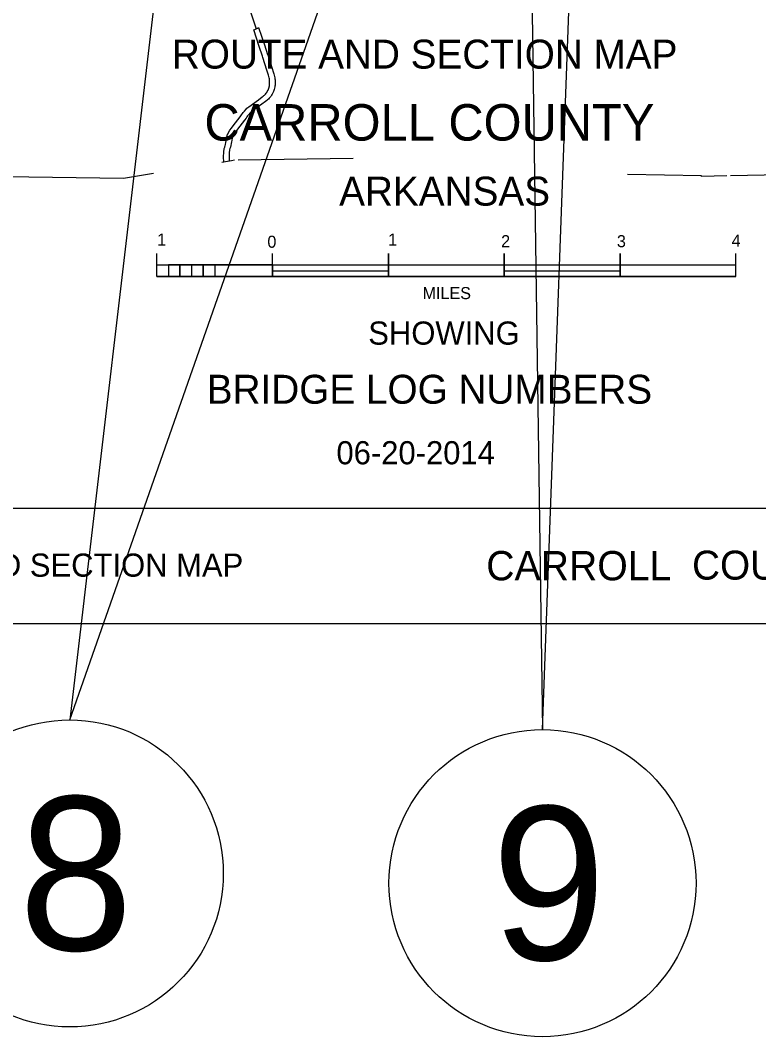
# Model space of a CAD drawing. Extents: x 77230 to 630905, y 790554 to 1662844.
# Drawn here: x 544436 to 578093, y 1464500 to 1510846 of the extents above; entities that cross this region are included whole.
import ezdxf

# ---------------------------------------------------------------- set-up
doc = ezdxf.new("R2010")
doc.units = 0
for name, color, linetype in [('Level 10', 7, 'Continuous'), ('Level 28', 7, 'Continuous'), ('Level 41', 7, 'Continuous'), ('Level 43', 7, 'Continuous')]:
    doc.layers.add(name, color=color, linetype=linetype)

msp = doc.modelspace()

# ---------------------------------------------------------------- linework, layer by layer
at = {"layer": 'Level 10'}
for points in [[(554148, 1513919), (554167, 1513776), (554228, 1513500), (554320, 1513168), (554737, 1511840), (555112, 1510683)], [(553709, 1504836), (553714, 1504879), (553719, 1504915), (553724, 1504948), (553735, 1504998), (553752, 1505059), (553761, 1505094), (553769, 1505124), (553781, 1505182), (553798, 1505274), (553816, 1505353), (553827, 1505409), (553850, 1505541), (553858, 1505578), (553872, 1505620), (553891, 1505662), (553932, 1505731), (553992, 1505830), (554056, 1505924), (554144, 1506035), (554457, 1506448), (554523, 1506537), (554567, 1506596), (554599, 1506638), (554654, 1506708), (554725, 1506793), (554768, 1506837), (554810, 1506874), (554853, 1506908), (555292, 1507223), (555466, 1507352), (555512, 1507387), (555543, 1507412), (555572, 1507437), (555598, 1507463), (555614, 1507480), (555644, 1507520), (555671, 1507562), (555694, 1507602), (555728, 1507660), (555740, 1507681), (555748, 1507697), (555753, 1507714), (555762, 1507748), (555790, 1507866), (555796, 1507890), (555799, 1507916), (555801, 1507958), (555800, 1508043), (555797, 1508122), (555793, 1508153), (555789, 1508185), (555781, 1508222), (555749, 1508341), (555721, 1508430), (555678, 1508569), (555494, 1509146), (555473, 1509207), (555322, 1509655), (555073, 1510405)], [(555299, 1510518), (555559, 1509734), (555710, 1509287), (555731, 1509224), (555916, 1508644), (555960, 1508504), (555989, 1508411), (556023, 1508282), (556035, 1508231), (556041, 1508184), (556046, 1508140), (556050, 1508049), (556051, 1507954), (556048, 1507894), (556042, 1507845), (556033, 1507809), (556005, 1507688), (555993, 1507644), (555980, 1507604), (555961, 1507564), (555944, 1507535), (555911, 1507477), (555884, 1507431), (555849, 1507377), (555808, 1507322), (555779, 1507290), (555742, 1507253), (555703, 1507220), (555666, 1507190), (555616, 1507152), (555440, 1507021), (555003, 1506708), (554971, 1506683), (554940, 1506655), (554910, 1506624), (554848, 1506551), (554796, 1506484), (554766, 1506445), (554723, 1506388), (554657, 1506298), (554341, 1505882), (554257, 1505776), (554202, 1505696), (554147, 1505603), (554113, 1505546), (554105, 1505530), (554100, 1505513), (554096, 1505494), (554073, 1505362), (554060, 1505300), (554043, 1505223), (554026, 1505135), (554013, 1505067), (554003, 1505029), (553993, 1504994), (553978, 1504939), (553970, 1504901), (553966, 1504876), (553962, 1504847), (553959, 1504820)], [(555112, 1510683), (555187, 1510458)], [(553959, 1504424), (553710, 1504383), (553704, 1504617), (553709, 1504836)], [(553959, 1504820), (553954, 1504617), (553959, 1504424)]]:
    msp.add_lwpolyline(points, dxfattribs=at)
msp.add_arc((554369, 1512098), 1833, 292.5727, 300.4716, dxfattribs=at)
at = {"layer": 'Level 28'}
for p, q in [((550656, 1499692), (550656, 1500220)), ((555936, 1499692), (555936, 1500220)), ((561216, 1499692), (561216, 1500220)), ((561216, 1500220), (561216, 1499692)), ((566496, 1499692), (566496, 1500220)), ((566496, 1500220), (566496, 1499692)), ((571776, 1499692), (571776, 1500220)), ((571776, 1500220), (571776, 1499692)), ((577056, 1499164), (577056, 1500220)), ((550656, 1499164), (550656, 1499692)), ((550656, 1499692), (550656, 1499692)), ((550656, 1499692), (555936, 1499692)), ((550656, 1499692), (551184, 1499692)), ((551184, 1499692), (551184, 1499692)), ((551712, 1499692), (551184, 1499692)), ((551184, 1499692), (551184, 1499692)), ((551184, 1499692), (551184, 1499164)), ((552240, 1499692), (551712, 1499692)), ((551712, 1499692), (551712, 1499692)), ((551712, 1499692), (551712, 1499692)), ((551712, 1499692), (551712, 1499164)), ((551712, 1499164), (551712, 1499692)), ((552768, 1499692), (552240, 1499692)), ((552240, 1499692), (552240, 1499692)), ((552240, 1499692), (552240, 1499692)), ((552240, 1499692), (552240, 1499164)), ((553296, 1499692), (552768, 1499692)), ((552768, 1499692), (552768, 1499692)), ((552768, 1499692), (552768, 1499164)), ((552768, 1499164), (552768, 1499692)), ((553296, 1499692), (553373, 1499697)), ((555936, 1499692), (553296, 1499692)), ((553296, 1499692), (553296, 1499164)), ((555936, 1499692), (555936, 1499692)), ((555936, 1499692), (555936, 1499164)), ((555936, 1499164), (555936, 1499692)), ((555936, 1499692), (561216, 1499692)), ((555936, 1499164), (555936, 1499428)), ((555936, 1499428), (555936, 1499428)), ((555936, 1499428), (561216, 1499428)), ((561216, 1499692), (561216, 1499164)), ((561216, 1499164), (561216, 1499692)), ((561216, 1499692), (566496, 1499692)), ((566496, 1499692), (566496, 1499692)), ((566496, 1499692), (566496, 1499164)), ((566496, 1499164), (566496, 1499692)), ((566496, 1499692), (571776, 1499692)), ((566496, 1499164), (566496, 1499420)), ((566496, 1499420), (566496, 1499420)), ((566496, 1499420), (571776, 1499420)), ((571776, 1499692), (571776, 1499164)), ((571776, 1499164), (571776, 1499692)), ((571776, 1499692), (577056, 1499692)), ((550656, 1499164), (577056, 1499164)), ((577056, 1499164), (550656, 1499164)), ((311736, 1488604), (586296, 1488604)), ((591576, 1483324), (295896, 1483324))]:
    msp.add_line(p, q, dxfattribs=at)
at = {"layer": 'Level 41'}
for points in [[(567679, 1517517), (568239, 1478500), (569738, 1519525)], [(550532, 1511658), (546688, 1478945), (558497, 1512665)]]:
    msp.add_lwpolyline(points, dxfattribs=at)
for centre in [(546688, 1471945), (568239, 1471500)]:
    msp.add_circle(centre, 7000, dxfattribs=at)
at = {"layer": 'Level 43'}
for points in [[(553709, 1504383), (553614, 1504367)], [(554055, 1504440), (553973, 1504426)], [(554204, 1504465), (554055, 1504440)], [(559611, 1504543), (554360, 1504475)], [(550513, 1503855), (549139, 1503629), (543739, 1503707), (543107, 1503717)], [(576641, 1503750), (575485, 1503727), (575485, 1503753), (572118, 1503814)], [(584379, 1503890), (580655, 1503830), (580648, 1503830), (576808, 1503754)]]:
    msp.add_lwpolyline(points, dxfattribs=at)

# ---------------------------------------------------------------- texts
at = {"layer": 'Level 28'}
for s, height, p in [('ROUTE AND SECTION MAP', 1320, (551344, 1508645)), ('CARROLL COUNTY', 1663, (552826, 1505361)), ('ARKANSAS', 1320, (558969, 1502397)), ('1', 550, (550672, 1500575)), ('0', 550, (555698, 1500476)), ('1', 550, (561204, 1500575)), ('2', 550, (566352, 1500500)), ('3', 550, (571631, 1500500)), ('4', 550, (576860, 1500525)), ('MILES', 550, (562771, 1498133)), ('SHOWING', 1056, (560297, 1496057)), ('BRIDGE LOG NUMBERS', 1320, (552933, 1493363)), ('06-20-2014', 1056, (558846, 1490600)), ('ROUTE AND SECTION MAP', 1056, (536161, 1485475)), ('CARROLL', 1336, (565674, 1485310)), ('COUNTY', 1320, (575056, 1485343))]:
    msp.add_text(s, height=height, dxfattribs=at).set_placement(p)
at = {"layer": 'Level 41'}
for s, p in [('8', (544364, 1468445)), ('9', (565922, 1468000))]:
    msp.add_text(s, height=7000, dxfattribs=at).set_placement(p)

doc.saveas('drawing.dxf')
